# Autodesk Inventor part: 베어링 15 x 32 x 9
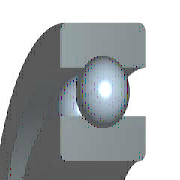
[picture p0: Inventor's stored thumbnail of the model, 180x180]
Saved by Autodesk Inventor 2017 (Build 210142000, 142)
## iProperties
IsCustomPart: 0
Created: 2012-02
Part Number: 베어링 15 x 32 x 9
Material: 강철, 연강
Description: 깊은 그루브 볼 베어링
Document SubType Name: Modeling
Standard: KS B 2023
Designer: mduedu
Standards Organization: KS
Language: ko-KR
Size Designation: 6002 - 15 x 32 x 9
Categories: <MemberInstance><Categories><Category DisplayName="샤프트 부품" InternalName="7f7aeb1f-a693-4053-b835-cee3144e0d98" Mnemonic="SHFT"><Category DisplayName="베어링" Inter
Density: 1 g/cm^3
Appearance: 노란색
Author: mduedu
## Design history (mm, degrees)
sketch "스케치" dims "d0" = 4.42 (= -0.26 x WD + 0.26 x BD)
  geometry: L1 (2.29, 11.75)-(6.71, 11.75); L2 (4.5, 11.75)-(4.5, 9.54); L3 (4.5, 11.75)-(4.5, 13.96); L4 (2.858, 10.271)-(0, 10.271); L5 (0, 7.5)-(9, 7.5); L6 (2.858, 13.229)-(0, 13.229); L7 (0, 16)-(9, 16); L8 (9, 7.5)-(9, 10.271); L9 (6.142, 10.271)-(9, 10.271); L10 (6.142, 13.229)-(9, 13.229); L11 (9, 16)-(9, 13.229); L12 (-1.4, 0)-(8.4, 0) reference; L13 (0, -0.3)-(0, 5.3) reference
  constraints: 22 end point, 4 point on line, 2 collinear, 2 perpendicular, 2 symmetric about line, 1 midpoint, 1 parallel, 14 other
  dimensions: "d9" = 15 diameter of L5 L12 (= WD); "d11" = 32 diameter of L7 L12 (= BD); "d12" = 9 distance between parallel lines of L8 L13 (= KB); "d13" = 20.542 diameter of L9 L12 (= 0.326 x BD + 0.674 x WD)
revolve "본체" stored, may be unused: angle "d6" = 90 deg
revolve "볼" stored, may be unused: angle "d7" = 90 deg
pattern_circular "IDS_ARRAYBALL[SIMPL:T]" dims angle "d3" = 360 deg
body "Solid1"
fillet "모깎기1" dims "d1" = 0.3 (= KRS)
other parameters: "WD" = 15 [user parameter; used in 5 equation terms], "BD" = 32 [user parameter; used in 5 equation terms], "KB" = 9 [user parameter; used in 1 equation term], "KRS" = 0.3 [user parameter; used in 1 equation term], "d4" = 0, "d5" = 0, "d8" = 0, "d14" = 0, "d15" = 0, "BBA" = 0 [user parameter], "BC0" = 2850000 [user parameter], "BC" = 5590000 [user parameter], "BR" = 16 (= 0.5 x BD) [user parameter], "WR" = 7.5 (= 0.5 x WD) [user parameter]
